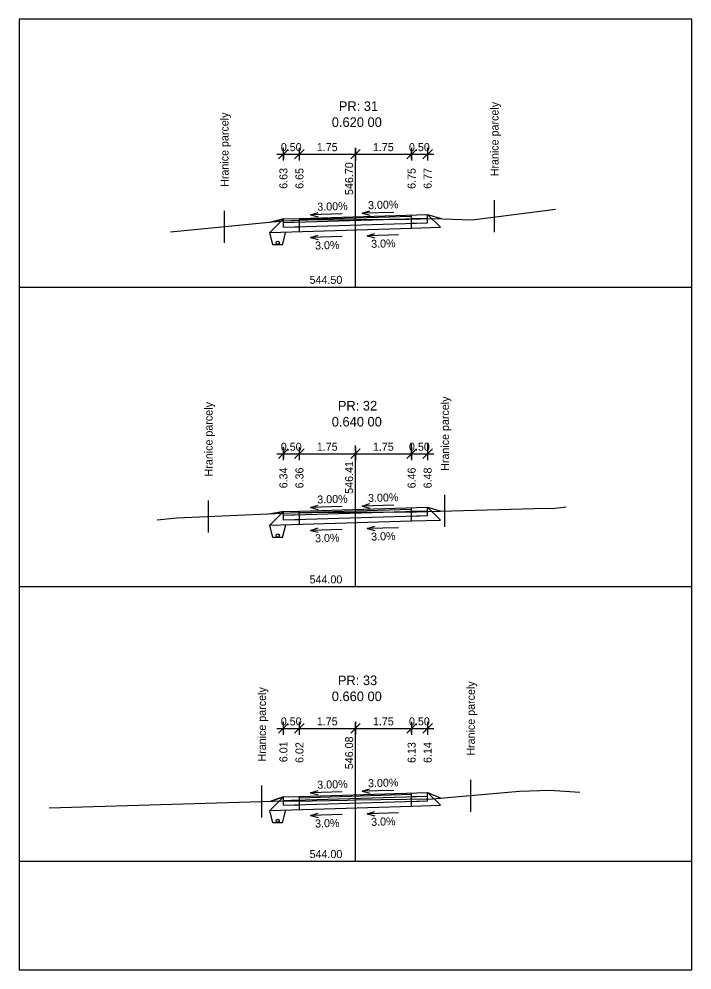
# Model space of a CAD drawing. Extents: x -603737 to -603383, y -1112154 to -1112124.
# Drawn here: x -603454.62 to -603433.62, y -1112153.84 to -1112124.14 of the extents above; entities that cross this region are included whole.
import ezdxf

# ---------------------------------------------------------------- set-up
doc = ezdxf.new("R2010")
doc.units = 0
for name, color, linetype in [('_křivky z hran', 7, 'Continuous'), ('_netisk', 7, 'Continuous'), ('C3D_Podsestava-Popis', 7, 'Continuous'), ('C3D_PP-Popisek', 7, 'Continuous'), ('C3D_PR', 7, 'Continuous'), ('C3D_ZPR', 7, 'Continuous'), ('Default', 7, 'Continuous'), ('konstrukce', 7, 'Continuous')]:
    doc.layers.add(name, color=color, linetype=linetype)

# ---------------------------------------------------------------- blocks, each defined once
blk = doc.blocks.new('_Oblique')
at = {"layer": 'Default'}
blk.add_line((-0.5, -0.5), (0.5, 0.5), dxfattribs=at)
blk = doc.blocks.new('AeccTickLine')
at = {"layer": 'Default'}
blk.add_line((0, 1), (0, -1), dxfattribs=at)

msp = doc.modelspace()

# ---------------------------------------------------------------- linework, layer by layer
at = {"layer": '_netisk'}
msp.add_lwpolyline([(-603454.62, -1112153.84), (-603433.62, -1112153.84), (-603433.62, -1112124.14), (-603454.62, -1112124.14)], close=True, dxfattribs=at)
at = {"layer": 'C3D_Podsestava-Popis'}
for p, q in [((-603446.57, -1112128.361), (-603444.12, -1112128.361)), ((-603445.87, -1112128.511), (-603445.87, -1112128.366)), ((-603444.12, -1112128.511), (-603444.12, -1112128.314)), ((-603444.12, -1112128.361), (-603441.67, -1112128.361)), ((-603442.37, -1112128.511), (-603442.37, -1112128.261)), ((-603441.87, -1112128.246), (-603441.87, -1112128.511)), ((-603446.37, -1112128.381), (-603446.37, -1112128.511)), ((-603446.37, -1112137.525), (-603446.37, -1112137.867)), ((-603445.87, -1112137.867), (-603445.87, -1112137.51)), ((-603444.12, -1112137.867), (-603444.12, -1112137.457)), ((-603442.37, -1112137.867), (-603442.37, -1112137.405)), ((-603441.87, -1112137.39), (-603441.87, -1112137.867)), ((-603446.57, -1112137.717), (-603444.12, -1112137.717)), ((-603444.12, -1112137.717), (-603441.67, -1112137.717)), ((-603446.57, -1112146.294), (-603444.12, -1112146.294)), ((-603446.37, -1112146.434), (-603446.37, -1112146.444)), ((-603445.87, -1112146.444), (-603445.87, -1112146.419)), ((-603444.12, -1112146.294), (-603441.67, -1112146.294)), ((-603444.12, -1112146.444), (-603444.12, -1112146.366)), ((-603442.37, -1112146.444), (-603442.37, -1112146.314)), ((-603441.87, -1112146.299), (-603441.87, -1112146.444))]:
    msp.add_line(p, q, dxfattribs=at)
at = {"layer": 'C3D_PP-Popisek'}
for p, q in [((-603443.911, -1112130.207), (-603443.675, -1112130.132)), ((-603445.522, -1112130.256), (-603445.286, -1112130.18)), ((-603444.539, -1112130.226), (-603445.522, -1112130.256)), ((-603445.522, -1112130.256), (-603445.282, -1112130.317)), ((-603442.927, -1112130.178), (-603443.911, -1112130.207)), ((-603443.911, -1112130.207), (-603443.671, -1112130.268)), ((-603445.522, -1112130.966), (-603445.286, -1112130.89)), ((-603444.539, -1112130.936), (-603445.522, -1112130.966)), ((-603445.522, -1112130.966), (-603445.282, -1112131.027)), ((-603443.758, -1112130.913), (-603443.521, -1112130.837)), ((-603442.774, -1112130.883), (-603443.758, -1112130.913)), ((-603443.758, -1112130.913), (-603443.517, -1112130.974)), ((-603445.522, -1112139.399), (-603445.286, -1112139.324)), ((-603443.911, -1112139.351), (-603443.675, -1112139.276)), ((-603442.927, -1112139.321), (-603443.911, -1112139.351)), ((-603443.911, -1112139.351), (-603443.671, -1112139.412)), ((-603444.539, -1112139.37), (-603445.522, -1112139.399)), ((-603445.522, -1112139.399), (-603445.282, -1112139.46)), ((-603445.522, -1112140.11), (-603445.286, -1112140.034)), ((-603444.539, -1112140.08), (-603445.522, -1112140.11)), ((-603445.522, -1112140.11), (-603445.282, -1112140.171)), ((-603443.758, -1112140.057), (-603443.521, -1112139.981)), ((-603442.774, -1112140.027), (-603443.758, -1112140.057)), ((-603443.758, -1112140.057), (-603443.517, -1112140.118)), ((-603445.522, -1112148.308), (-603445.286, -1112148.233)), ((-603444.539, -1112148.279), (-603445.522, -1112148.308)), ((-603443.911, -1112148.26), (-603443.675, -1112148.185)), ((-603442.927, -1112148.23), (-603443.911, -1112148.26)), ((-603443.911, -1112148.26), (-603443.671, -1112148.321)), ((-603445.522, -1112148.308), (-603445.282, -1112148.369)), ((-603445.522, -1112149.019), (-603445.286, -1112148.943)), ((-603444.539, -1112148.989), (-603445.522, -1112149.019)), ((-603445.522, -1112149.019), (-603445.282, -1112149.08)), ((-603443.758, -1112148.966), (-603443.521, -1112148.89)), ((-603442.774, -1112148.936), (-603443.758, -1112148.966)), ((-603443.758, -1112148.966), (-603443.517, -1112149.027))]:
    msp.add_line(p, q, dxfattribs=at)
at = {"layer": 'C3D_PR'}
for points in [[(-603449.892, -1112130.787), (-603446.384, -1112130.446), (-603445.621, -1112130.413), (-603444.12, -1112130.401), (-603443.067, -1112130.393), (-603442.453, -1112130.388), (-603441.701, -1112130.366), (-603441.701, -1112130.366), (-603440.478, -1112130.409), (-603437.881, -1112130.078)], [(-603450.307, -1112139.778), (-603449.693, -1112139.718), (-603445.906, -1112139.557), (-603445.467, -1112139.553), (-603444.12, -1112139.545), (-603442.217, -1112139.533), (-603438.168, -1112139.419), (-603438.168, -1112139.419), (-603437.967, -1112139.426), (-603437.544, -1112139.372)], [(-603453.679, -1112148.775), (-603446.696, -1112148.571), (-603445.468, -1112148.557), (-603444.369, -1112148.534), (-603444.12, -1112148.531), (-603441.72, -1112148.499), (-603439.004, -1112148.253), (-603438.056, -1112148.226), (-603438.056, -1112148.226), (-603437.118, -1112148.289), (-603437.118, -1112148.289)]]:
    msp.add_lwpolyline(points, dxfattribs=at)
at = {"layer": 'C3D_ZPR'}
for p, q in [((-603444.12, -1112132.511), (-603444.12, -1112128.511)), ((-603439.78, -1112130.802), (-603439.78, -1112129.802)), ((-603448.207, -1112131.133), (-603448.207, -1112130.133)), ((-603446.792, -1112130.804), (-603446.37, -1112130.381)), ((-603446.37, -1112130.381), (-603446.765, -1112130.483)), ((-603446.765, -1112130.483), (-603446.37, -1112130.381)), ((-603446.37, -1112130.491), (-603441.87, -1112130.356)), ((-603446.37, -1112130.381), (-603445.87, -1112130.366)), ((-603446.37, -1112130.641), (-603446.37, -1112130.381)), ((-603446.37, -1112130.641), (-603446.37, -1112130.381)), ((-603445.87, -1112130.366), (-603441.87, -1112130.246)), ((-603445.87, -1112130.406), (-603442.37, -1112130.301)), ((-603445.87, -1112130.776), (-603445.87, -1112130.366)), ((-603445.87, -1112130.476), (-603445.87, -1112130.406)), ((-603442.37, -1112130.301), (-603442.37, -1112130.261)), ((-603442.37, -1112130.671), (-603442.37, -1112130.261)), ((-603442.37, -1112130.371), (-603441.87, -1112130.356)), ((-603442.37, -1112130.521), (-603442.37, -1112130.371)), ((-603441.87, -1112130.506), (-603441.87, -1112130.246)), ((-603441.87, -1112130.506), (-603441.87, -1112130.246)), ((-603441.87, -1112130.246), (-603441.471, -1112130.644)), ((-603441.87, -1112130.246), (-603441.445, -1112130.375)), ((-603441.87, -1112130.246), (-603441.445, -1112130.375)), ((-603446.792, -1112130.804), (-603442.37, -1112130.671)), ((-603446.37, -1112130.491), (-603445.87, -1112130.476)), ((-603446.37, -1112130.641), (-603441.87, -1112130.506)), ((-603446.37, -1112130.641), (-603445.87, -1112130.626)), ((-603445.87, -1112130.776), (-603445.87, -1112130.626)), ((-603442.37, -1112130.521), (-603441.87, -1112130.506)), ((-603442.37, -1112130.671), (-603441.471, -1112130.644)), ((-603454.62, -1112132.511), (-603433.62, -1112132.511)), ((-603444.12, -1112141.867), (-603444.12, -1112137.867)), ((-603441.327, -1112140.002), (-603441.327, -1112139.002)), ((-603448.705, -1112140.176), (-603448.705, -1112139.176)), ((-603446.792, -1112139.948), (-603446.37, -1112139.525)), ((-603446.37, -1112139.525), (-603446.765, -1112139.593)), ((-603446.765, -1112139.593), (-603446.37, -1112139.525)), ((-603446.37, -1112139.635), (-603441.87, -1112139.5)), ((-603446.37, -1112139.525), (-603445.87, -1112139.51)), ((-603446.37, -1112139.785), (-603446.37, -1112139.525)), ((-603446.37, -1112139.785), (-603446.37, -1112139.525)), ((-603446.37, -1112139.635), (-603445.87, -1112139.62)), ((-603446.37, -1112139.785), (-603441.87, -1112139.65)), ((-603445.87, -1112139.51), (-603441.87, -1112139.39)), ((-603445.87, -1112139.55), (-603442.37, -1112139.445)), ((-603445.87, -1112139.92), (-603445.87, -1112139.51)), ((-603445.87, -1112139.62), (-603445.87, -1112139.55)), ((-603442.37, -1112139.445), (-603442.37, -1112139.405)), ((-603442.37, -1112139.815), (-603442.37, -1112139.405)), ((-603442.37, -1112139.515), (-603441.87, -1112139.5)), ((-603442.37, -1112139.665), (-603442.37, -1112139.515)), ((-603442.37, -1112139.665), (-603441.87, -1112139.65)), ((-603441.87, -1112139.65), (-603441.87, -1112139.39)), ((-603441.87, -1112139.65), (-603441.87, -1112139.39)), ((-603441.87, -1112139.39), (-603441.471, -1112139.788)), ((-603441.87, -1112139.39), (-603441.445, -1112139.511)), ((-603441.87, -1112139.39), (-603441.445, -1112139.511)), ((-603446.792, -1112139.948), (-603442.37, -1112139.815)), ((-603446.37, -1112139.785), (-603445.87, -1112139.77)), ((-603445.87, -1112139.92), (-603445.87, -1112139.77)), ((-603442.37, -1112139.815), (-603441.471, -1112139.788)), ((-603454.62, -1112141.867), (-603433.62, -1112141.867)), ((-603444.12, -1112150.444), (-603444.12, -1112146.444)), ((-603440.521, -1112148.897), (-603440.521, -1112147.897)), ((-603447.039, -1112149.081), (-603447.039, -1112148.081)), ((-603446.792, -1112148.857), (-603446.37, -1112148.434)), ((-603446.37, -1112148.434), (-603446.765, -1112148.573)), ((-603446.765, -1112148.573), (-603446.37, -1112148.434)), ((-603446.37, -1112148.544), (-603441.87, -1112148.409)), ((-603446.37, -1112148.434), (-603445.87, -1112148.419)), ((-603446.37, -1112148.694), (-603446.37, -1112148.434)), ((-603446.37, -1112148.694), (-603446.37, -1112148.434)), ((-603446.37, -1112148.544), (-603445.87, -1112148.529)), ((-603446.37, -1112148.694), (-603441.87, -1112148.559)), ((-603445.87, -1112148.419), (-603441.87, -1112148.299)), ((-603445.87, -1112148.459), (-603442.37, -1112148.354)), ((-603445.87, -1112148.829), (-603445.87, -1112148.419)), ((-603445.87, -1112148.529), (-603445.87, -1112148.459)), ((-603442.37, -1112148.354), (-603442.37, -1112148.314)), ((-603442.37, -1112148.724), (-603442.37, -1112148.314)), ((-603442.37, -1112148.424), (-603441.87, -1112148.409)), ((-603442.37, -1112148.574), (-603442.37, -1112148.424)), ((-603442.37, -1112148.574), (-603441.87, -1112148.559)), ((-603441.87, -1112148.559), (-603441.87, -1112148.299)), ((-603441.87, -1112148.559), (-603441.87, -1112148.299)), ((-603441.87, -1112148.299), (-603441.471, -1112148.697)), ((-603441.87, -1112148.299), (-603441.445, -1112148.474)), ((-603441.87, -1112148.299), (-603441.445, -1112148.474)), ((-603446.792, -1112148.857), (-603442.37, -1112148.724)), ((-603446.37, -1112148.694), (-603445.87, -1112148.679)), ((-603445.87, -1112148.829), (-603445.87, -1112148.679)), ((-603442.37, -1112148.724), (-603441.471, -1112148.697)), ((-603454.62, -1112150.444), (-603433.62, -1112150.444))]:
    msp.add_line(p, q, dxfattribs=at)
at = {"layer": 'konstrukce'}
for p, q in [((-603446.696, -1112131.189), (-603446.792, -1112130.804)), ((-603446.396, -1112131.189), (-603446.296, -1112130.789)), ((-603446.396, -1112131.189), (-603446.696, -1112131.189)), ((-603446.696, -1112140.333), (-603446.792, -1112139.948)), ((-603446.396, -1112140.333), (-603446.296, -1112139.933)), ((-603446.396, -1112140.333), (-603446.696, -1112140.333)), ((-603446.696, -1112149.242), (-603446.792, -1112148.857)), ((-603446.396, -1112149.242), (-603446.296, -1112148.842)), ((-603446.396, -1112149.242), (-603446.696, -1112149.242))]:
    msp.add_line(p, q, dxfattribs=at)
for centre in [(-603446.546, -1112131.129), (-603446.546, -1112140.273), (-603446.546, -1112149.182)]:
    msp.add_circle(centre, 0.05, dxfattribs=at)

# ---------------------------------------------------------------- block references
at = {"layer": '_křivky z hran', "rotation": 180}
for name, p, xscale, yscale in [('_Oblique', (-603446.37, -1112128.361), 0.3, 0.3), ('AeccTickLine', (-603446.37, -1112128.361), 0.2, 0.20000000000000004), ('_Oblique', (-603445.87, -1112128.361), 0.3, 0.3), ('AeccTickLine', (-603445.87, -1112128.361), 0.2, 0.20000000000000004), ('_Oblique', (-603444.12, -1112128.361), 0.3, 0.3), ('AeccTickLine', (-603444.12, -1112128.361), 0.2, 0.20000000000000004), ('_Oblique', (-603446.37, -1112137.717), 0.3, 0.3), ('AeccTickLine', (-603446.37, -1112137.717), 0.2, 0.20000000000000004), ('_Oblique', (-603445.87, -1112137.717), 0.3, 0.3), ('AeccTickLine', (-603445.87, -1112137.717), 0.2, 0.20000000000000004), ('_Oblique', (-603444.12, -1112137.717), 0.3, 0.3), ('AeccTickLine', (-603444.12, -1112137.717), 0.2, 0.20000000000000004), ('_Oblique', (-603446.37, -1112146.294), 0.3, 0.3), ('AeccTickLine', (-603446.37, -1112146.294), 0.2, 0.20000000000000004), ('_Oblique', (-603445.87, -1112146.294), 0.3, 0.3), ('AeccTickLine', (-603445.87, -1112146.294), 0.2, 0.20000000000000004), ('_Oblique', (-603444.12, -1112146.294), 0.3, 0.3), ('AeccTickLine', (-603444.12, -1112146.294), 0.2, 0.20000000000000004)]:
    msp.add_blockref(name, p, dxfattribs=dict(at, xscale=xscale, yscale=yscale))
at = {"layer": '_křivky z hran'}
for name, p, xscale, yscale in [('_Oblique', (-603444.12, -1112128.361), 0.3, 0.3), ('AeccTickLine', (-603444.12, -1112128.361), 0.2, 0.20000000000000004), ('_Oblique', (-603442.37, -1112128.361), 0.3, 0.3), ('AeccTickLine', (-603442.37, -1112128.361), 0.2, 0.20000000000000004), ('_Oblique', (-603441.87, -1112128.361), 0.3, 0.3), ('AeccTickLine', (-603441.87, -1112128.361), 0.2, 0.20000000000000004), ('_Oblique', (-603444.12, -1112137.717), 0.3, 0.3), ('AeccTickLine', (-603444.12, -1112137.717), 0.2, 0.20000000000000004), ('_Oblique', (-603442.37, -1112137.717), 0.3, 0.3), ('AeccTickLine', (-603442.37, -1112137.717), 0.2, 0.20000000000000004), ('_Oblique', (-603441.87, -1112137.717), 0.3, 0.3), ('AeccTickLine', (-603441.87, -1112137.717), 0.2, 0.20000000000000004), ('_Oblique', (-603444.12, -1112146.294), 0.3, 0.3), ('AeccTickLine', (-603444.12, -1112146.294), 0.2, 0.20000000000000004), ('_Oblique', (-603442.37, -1112146.294), 0.3, 0.3), ('AeccTickLine', (-603442.37, -1112146.294), 0.2, 0.20000000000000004), ('_Oblique', (-603441.87, -1112146.294), 0.3, 0.3), ('AeccTickLine', (-603441.87, -1112146.294), 0.2, 0.20000000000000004)]:
    msp.add_blockref(name, p, dxfattribs=dict(at, xscale=xscale, yscale=yscale))

# ---------------------------------------------------------------- texts
at = {"layer": 'C3D_Podsestava-Popis'}
for s, rotation, p in [('0.50', 360, (-603446.451, -1112128.267)), ('1.75', 360, (-603445.327, -1112128.267)), ('1.75', 360, (-603445.327, -1112128.267)), ('1.75', 360, (-603443.577, -1112128.267)), ('1.75', 360, (-603443.577, -1112128.267)), ('0.50', 360, (-603442.451, -1112128.267)), ('546.70', 90, (-603444.194, -1112129.637)), ('6.63', 90, (-603446.244, -1112129.443)), ('6.63', 90, (-603446.244, -1112129.443)), ('6.65', 90, (-603445.744, -1112129.444)), ('6.75', 90, (-603442.244, -1112129.444)), ('6.77', 90, (-603441.744, -1112129.443)), ('6.77', 90, (-603441.744, -1112129.443)), ('3.00%', 1.7184, (-603445.309, -1112130.13)), ('3.00%', 1.7184, (-603443.725, -1112130.081)), ('3.0%', 1.7184, (-603443.628, -1112131.288)), ('3.0%', 1.7184, (-603445.378, -1112131.341)), ('0.50', 360, (-603446.451, -1112137.623)), ('1.75', 360, (-603445.327, -1112137.623)), ('1.75', 360, (-603445.327, -1112137.623)), ('1.75', 360, (-603443.577, -1112137.623)), ('1.75', 360, (-603443.577, -1112137.623)), ('0.50', 360, (-603442.451, -1112137.623)), ('6.34', 90, (-603446.244, -1112138.798)), ('6.34', 90, (-603446.244, -1112138.798)), ('6.36', 90, (-603445.744, -1112138.799)), ('546.41', 90, (-603444.194, -1112138.969)), ('6.46', 90, (-603442.244, -1112138.799)), ('6.48', 90, (-603441.744, -1112138.799)), ('6.48', 90, (-603441.744, -1112138.799)), ('3.00%', 1.7184, (-603445.309, -1112139.273)), ('3.00%', 1.7184, (-603443.725, -1112139.225)), ('3.0%', 1.7184, (-603445.378, -1112140.484)), ('3.0%', 1.7184, (-603443.628, -1112140.432)), ('0.50', 360, (-603446.451, -1112146.2)), ('1.75', 360, (-603445.327, -1112146.2)), ('1.75', 360, (-603445.327, -1112146.2)), ('1.75', 360, (-603443.577, -1112146.2)), ('1.75', 360, (-603443.577, -1112146.2)), ('0.50', 360, (-603442.451, -1112146.2)), ('6.01', 90, (-603446.244, -1112147.351)), ('6.01', 90, (-603446.244, -1112147.351)), ('6.02', 90, (-603445.744, -1112147.374)), ('546.08', 90, (-603444.194, -1112147.57)), ('6.13', 90, (-603442.244, -1112147.375)), ('6.14', 90, (-603441.744, -1112147.375)), ('6.14', 90, (-603441.744, -1112147.375)), ('3.00%', 1.7184, (-603445.309, -1112148.182)), ('3.00%', 1.7184, (-603443.725, -1112148.134)), ('3.0%', 1.7184, (-603445.378, -1112149.393)), ('3.0%', 1.7184, (-603443.628, -1112149.341))]:
    msp.add_text(s, height=0.25, rotation=rotation, dxfattribs=at).set_placement(p)
at = {"layer": 'C3D_ZPR'}
for s, p in [('PR: 31', (-603444.64, -1112127.011)), ('0.620 00', (-603444.86, -1112127.511)), ('PR: 32', (-603444.67, -1112136.367)), ('0.640 00', (-603444.86, -1112136.867)), ('PR: 33', (-603444.67, -1112144.944)), ('0.660 00', (-603444.86, -1112145.444))]:
    msp.add_text(s, height=0.3, dxfattribs=at).set_placement(p)
for s, rotation, p in [('Hranice parcely', 90, (-603439.655, -1112129.052)), ('Hranice parcely', 90, (-603448.082, -1112129.383)), ('544.50', 360, (-603445.553, -1112132.411)), ('Hranice parcely', 90, (-603441.202, -1112138.252)), ('Hranice parcely', 90, (-603448.58, -1112138.426)), ('544.00', 360, (-603445.553, -1112141.767)), ('Hranice parcely', 90, (-603446.914, -1112147.331)), ('Hranice parcely', 90, (-603440.396, -1112147.147)), ('544.00', 360, (-603445.553, -1112150.344))]:
    msp.add_text(s, height=0.25, rotation=rotation, dxfattribs=at).set_placement(p)

doc.saveas('drawing.dxf')
